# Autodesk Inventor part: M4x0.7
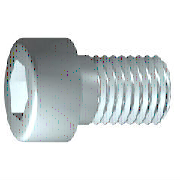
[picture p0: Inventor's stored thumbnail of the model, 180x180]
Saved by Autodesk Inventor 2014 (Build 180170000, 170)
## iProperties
Created: 2009-02
Part Number: M4x0.7
Material: 강, 연강
Description: 6각머리 태핑 나사
Document SubType Name: Modeling
Standard: KS B 1003
Standards Organization: KS
Language: ko-KR
Size Designation: M 4 x 12
Categories: <MemberInstance><Categories><Category DisplayName="조임쇠" InternalName="e4da775c-781d-43d5-af7c-5136215cf5a6" Mnemonic="FSTN"><Category DisplayName="볼트" InternalN
Density: 1 g/cm^3
Checked By: KYOUNG IL JANG
Vendor: CBT Solutions
Designer: KYOUNG IL JANG
Appearance: _시험-금속-강(연마)
Manager: KYOUNG IL JANG
Company: 한국ATC센터
IsCustomPart: 0
Author: KYOUNG IL JANG
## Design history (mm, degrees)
sketch "스케치1"
  geometry: L1 (-1, 0)-(12, 0); L2 (12, 0)-(12, 2); L3 (12, 2)-(1.75, 2); L4 (1.75, 2)-(1.32, 2); L5 (1.32, 2)-(0, 2); L6 (0, 2)-(0, 3.5); L7 (0, 3.5)-(-4, 3.5); L8 (-4, 3.5)-(-4, 1.732); L9 (-4, 1.732)-(-2, 1.732); L10 (-2, 1.732)-(-1, 0); L11 (-7.2, 0)-(15.2, 0) reference; L12 (0, -0.7)-(0, 4.2) reference; L13 (1.75, 2)-(0, 2)
  constraints: 22 end point, 6 parallel, 2 collinear, 2 perpendicular, 1 horizontal, 1 point on line
  dimensions: "d1" = 10.25 distance from line of L3.end L2 (= GEL); "d2" = 0.42952 distance of L4.end L3.end (computed from GAL); "d3" = 4 distance between parallel lines of L8 L6 (= KOH); "d4" = 2 distance of L8.end L9.end (= INTI); "d5" = 60 deg angle of L10 L1; "d6" = 4 diameter of L3 L1 (= GD); "d7" = 4 diameter of L5 L1 (= BDM); "d8" = 3.4641 diameter of L9 L1 (= 1.1547 x SW); "d9" = 7 diameter of L7 L1 (= KOD); "d26" = 12 distance between parallel lines of L12 L2 (= NLG)
revolve "본체" sketch "스케치1" stored, may be unused: angle "d10" = 90 deg
sketch "스케치2"
  geometry: L1 (0, -4.9)-(0, 4.9) reference; L2 (-4.9, 0)-(4.9, 0) reference; L3 (1.732, 0)-(0.866, -1.5); L4 (0.866, -1.5)-(-0.866, -1.5); L5 (-0.866, -1.5)-(-1.732, 0); L6 (-1.732, 0)-(-0.866, 1.5); L7 (-0.866, 1.5)-(0.866, 1.5); L8 (0.866, 1.5)-(1.732, 0); 2 further points
  constraints: 12 end point, 1 coincident, 1 horizontal alignment, 1 point on line, 12 other
extrude "슬롯" join sketch "스케치2" stored distance "d11" = 10; taper "d12" = 0 deg
workplane "Work Plane1"
fillet "Fillet2" dims "d30" = 0.1 (= R)
body "Solid1"
fillet "모깎기1" dims "d17" = 0.4 (= RR)
feature "스레드" dims "d13" = 10.25 (= GEL), "d14" = 0
chamfer "모따기1" distance "d15" = 0.42941 (= -0.5 x SPD + 0.5 x GD); stored, may be unused: second distance "d16" = 0.42941 (= GUL), angle "d27" = 45 deg
other parameters: "GD" = 4 (= NND) [user parameter; used in 2 equation terms], "NLG" = 12 [user parameter; used in 1 equation term], "GEL" = 10.25 [user parameter; used in 2 equation terms], "KOD" = 7 [user parameter; used in 1 equation term], "KOH" = 4 [user parameter; used in 1 equation term], "INTI" = 2 [user parameter; used in 1 equation term], "GAL" = 0.42941 (= 0.61345 x PTC) [user parameter; used in 1 equation term], "GUL" = 0.42941 (= 0.61345 x PTC) [user parameter; used in 1 equation term], "BDM" = 4 (= NND) [user parameter; used in 1 equation term], "SW" = 3 [user parameter; used in 2 equation terms], "RR" = 0.4 [user parameter; used in 1 equation term], "SPD" = 3.14117 (= NND - 1.2269 x PTC) [user parameter; used in 1 equation term], "d19" = 0, "d28" = 0, "d29" = 0, "R" = 0.1 [user parameter; used in 1 equation term], "PHH" = 0.2 [user parameter], "GD1" = 3.14117 (= THREADDIA - 1.2269 x PTC) [user parameter], "THREADDIA" = 4 [user parameter; used in 1 equation term], "FAWI" = 45 deg [user parameter], "TPU" = 14.28571 (computed from PTC) [user parameter], "PTC" = 0.7 [user parameter; used in 5 equation terms], "NND" = 4 [user parameter; used in 3 equation terms], "TOA" = 30 deg [user parameter], "E0" = 3.465 (= 1.155 x SW) [user parameter]
